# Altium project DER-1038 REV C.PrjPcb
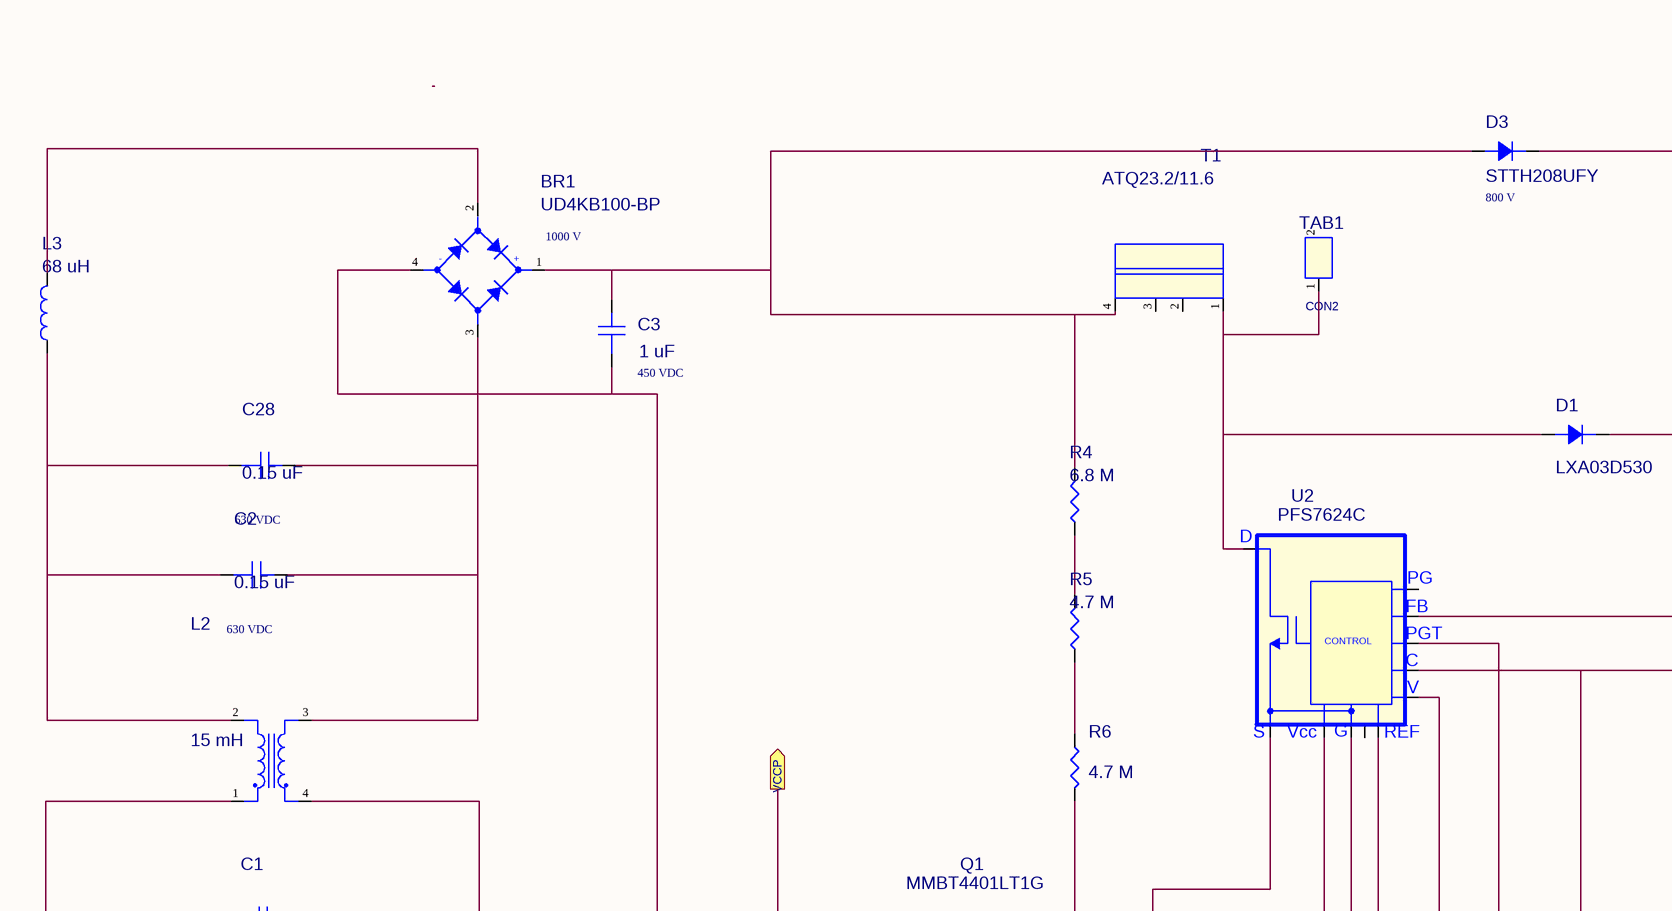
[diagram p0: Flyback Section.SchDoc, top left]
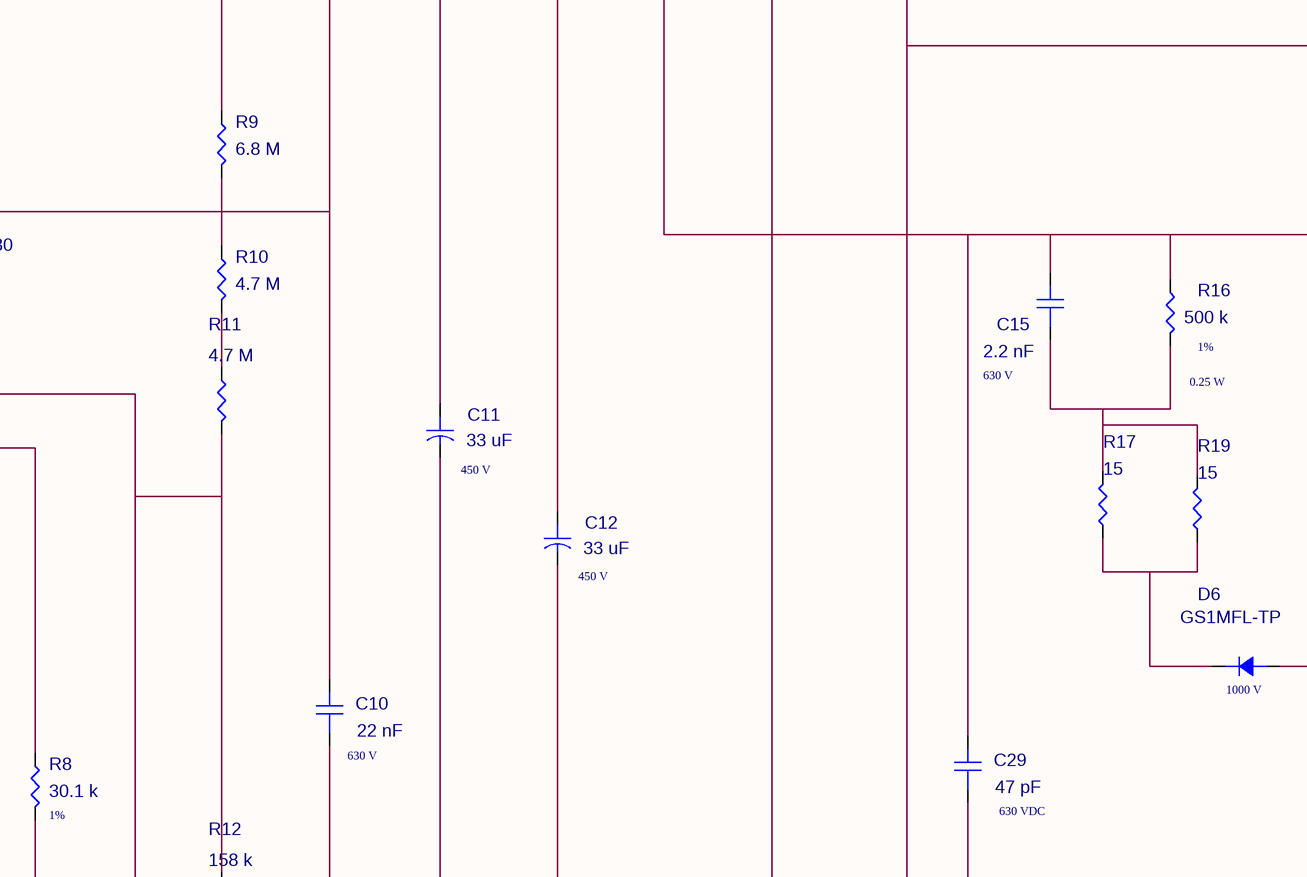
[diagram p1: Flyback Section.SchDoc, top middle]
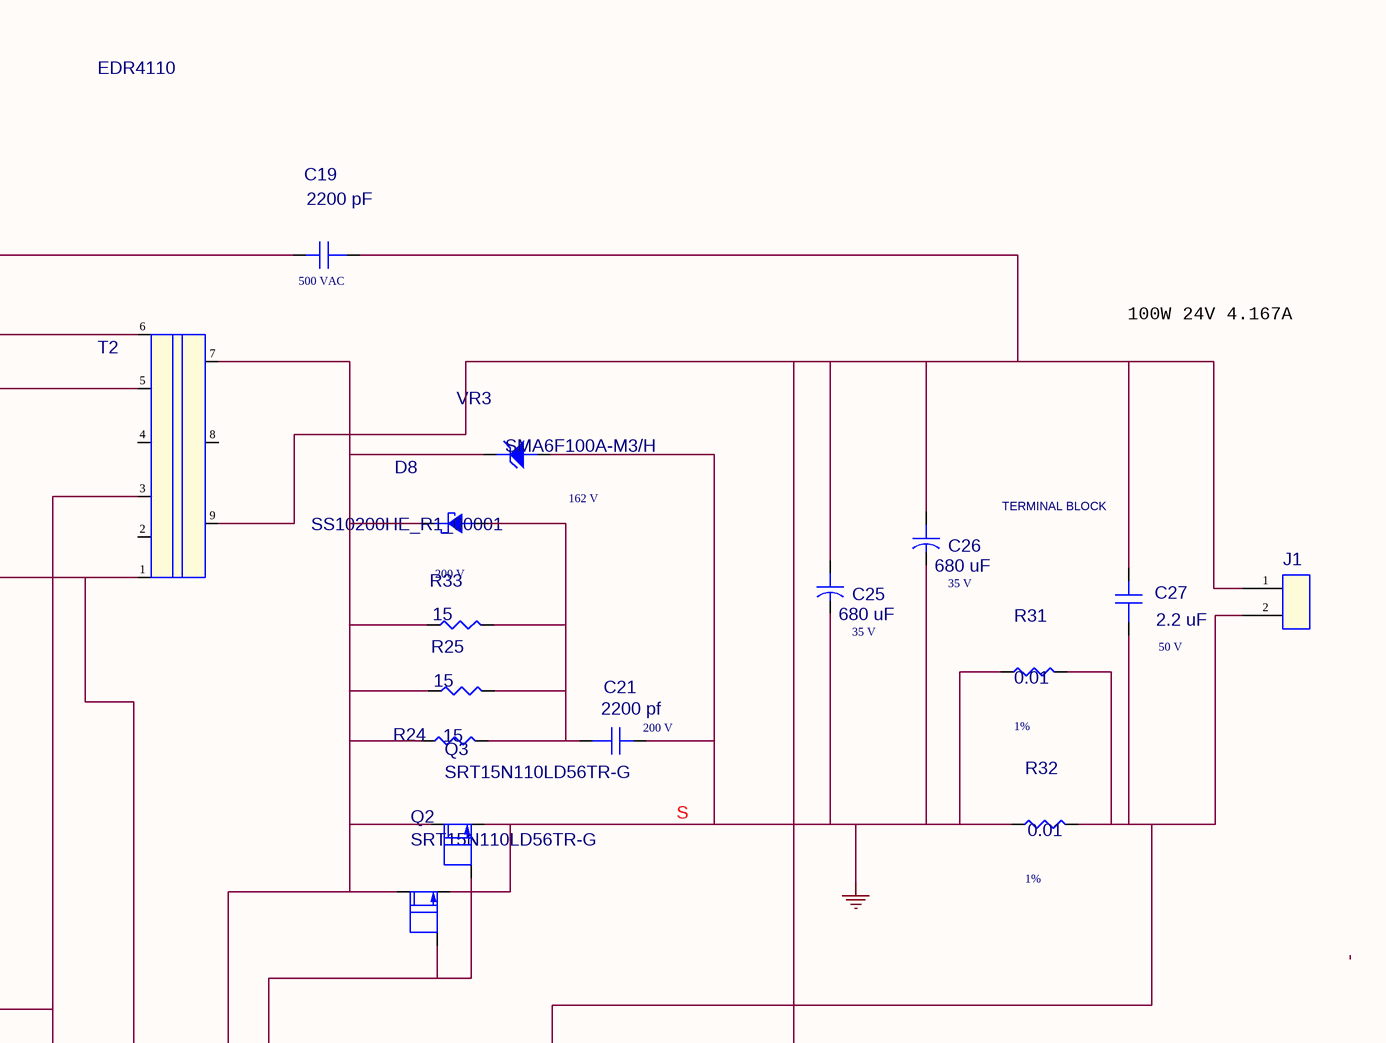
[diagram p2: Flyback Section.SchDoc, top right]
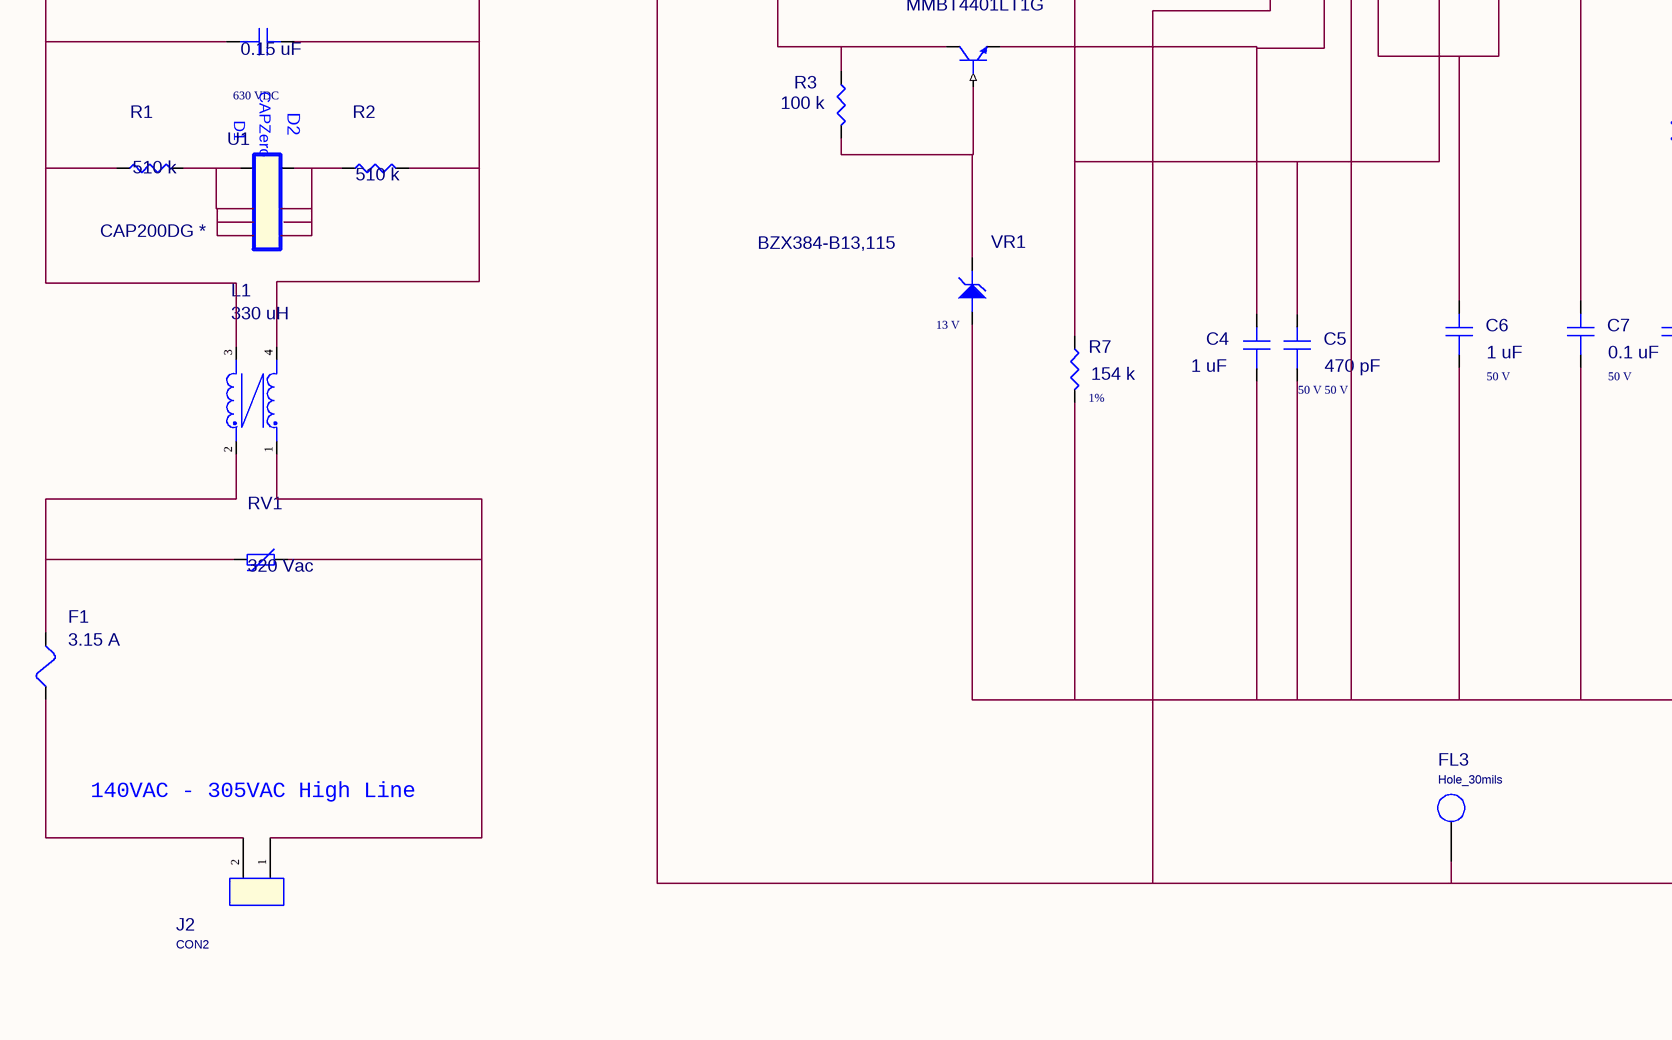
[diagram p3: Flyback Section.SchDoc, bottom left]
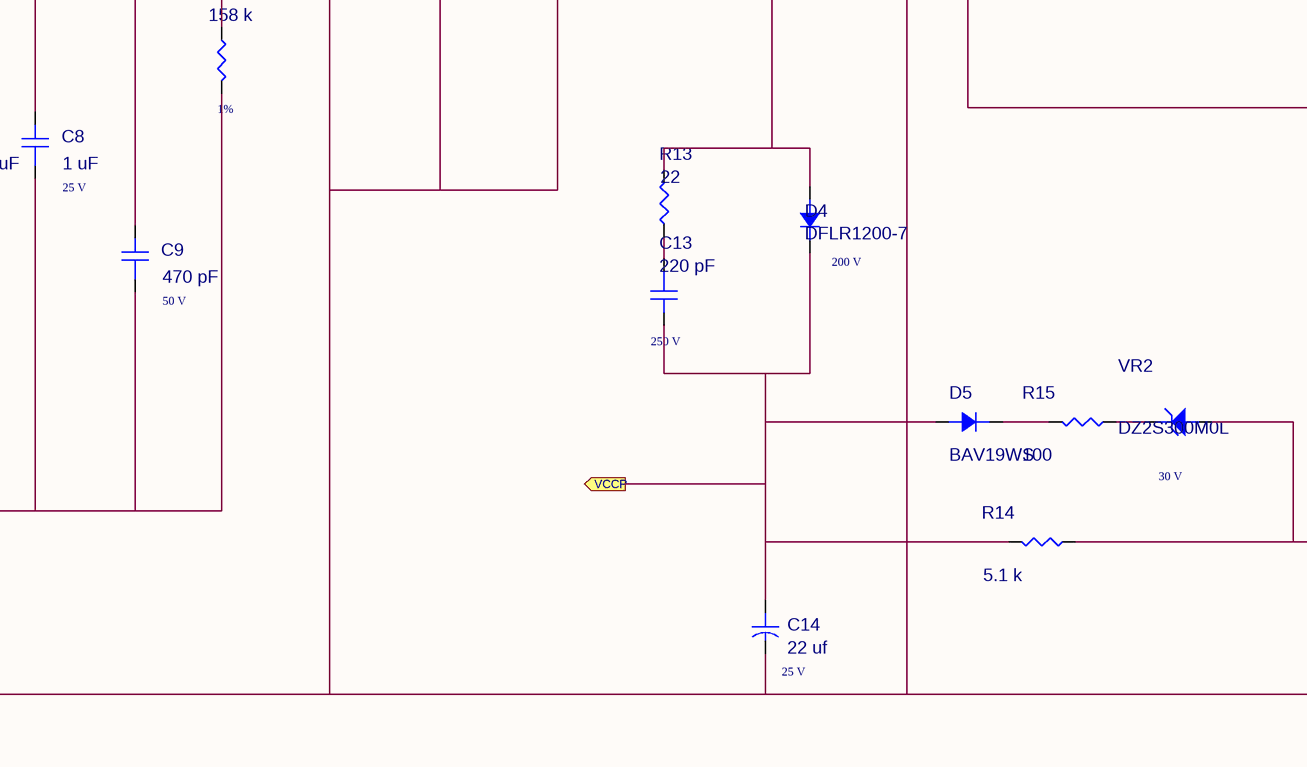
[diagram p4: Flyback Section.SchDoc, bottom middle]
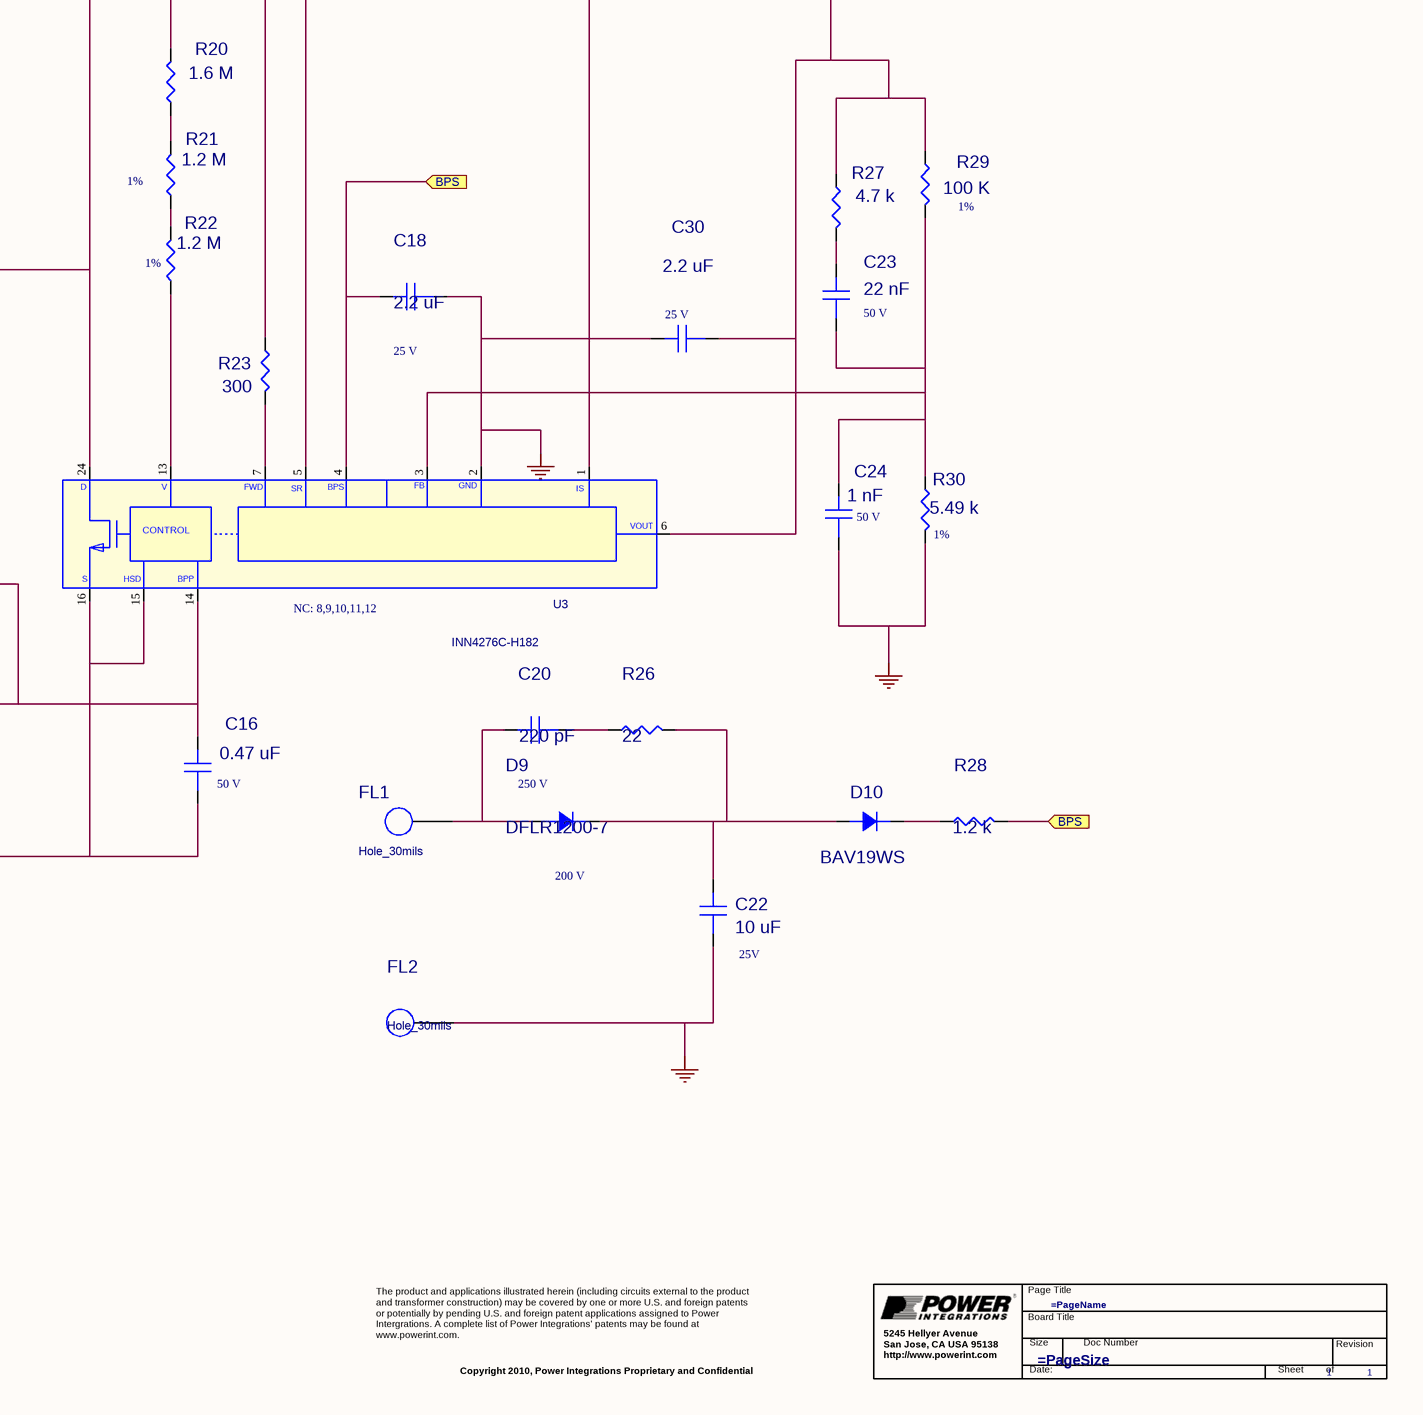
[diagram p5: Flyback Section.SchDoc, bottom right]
1 sheet, 93 parts. Net scope: flat (ports and power ports of the same name join across sheets).
Board file: DER-1038 REV C.PcbDoc

## Sheet Flyback Section.SchDoc
size 817 x 513 mm; Page Create Date: March  8, 1995; Page Number: 1; Page Size: D; Page Count: 1; Comment: TitleBlockPI_A-Sheet; Page Name: Flyback Section; DsnPath: F:\Apps_Files\Public\Design Example Reports\DER-1038 100W 24V HLO Inno4-QR\Schematic&PCB\Rev C\Altium\DER-1038 REV C.DSN; SchematicName: SCHEMATIC1; PageName: Flyback Section; PageSize: D; TopSchematic: True

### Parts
*  Page Count: 1  (hidden comment: TitleBlockPI_A-Sheet)  (graphical)
BR1  UD4KB100-BP  Disp_Voltage: 1000 V  [pidaxbridgeD3K]
C1  0.15 uF  Disp_Voltage: 630 VDC  [RAD/.250X.125/LS.200/.031]
C2  0.15 uF  Disp_Voltage: 630 VDC  [RAD/.250X.125/LS.200/.031]
C3  1 uF  Disp_Voltage: 450 VDC  [RAD/.250X.125/LS.200/.031]
C4  1 uF  Disp_Voltage: 50 V  [RAD/.250X.125/LS.200/.031]
C5  470 pF  Disp_Voltage: 50 V  [RAD/.250X.125/LS.200/.031]
C6  1 uF  Disp_Voltage: 50 V  [RAD/.250X.125/LS.200/.031]
C7  0.1 uF  Disp_Voltage: 50 V  [RAD/.250X.125/LS.200/.031]
C8  1 uF  Disp_Voltage: 25 V  [RAD/.250X.125/LS.200/.031]
C9  470 pF  Disp_Voltage: 50 V  [RAD/.250X.125/LS.200/.031]
C10  22 nF  Disp_Voltage: 630 V  [RAD/.250X.125/LS.200/.031]
C11  33 uF  Disp_Voltage: 450 V  [pipolcapd395ls200d0401705lh]
C12  33 uF  Disp_Voltage: 450 V  [pipolcapd395ls200d0401705lh]
C13  220 pF  Disp_Voltage: 250 V  [RAD/.250X.125/LS.200/.031]
C14  22 uf  Disp_Voltage: 25 V  [pi_polcap_d200_ls80_d030]
C15  2.2 nF  Disp_Voltage: 630 V  [RAD/.250X.125/LS.200/.031]
C16  0.47 uF  Disp_Voltage: 50 V  [RAD/.250X.125/LS.200/.031]
C18  2.2 uF  Disp_Voltage: 25 V  [RAD/.250X.125/LS.200/.031]
C19  2200 pF  Disp_Voltage: 500 VAC  [RAD/.250X.125/LS.200/.031]
C20  220 pF  Disp_Voltage: 250 V  [RAD/.250X.125/LS.200/.031]
C21  2200 pf  Disp_Voltage: 200 V  [RAD/.250X.125/LS.200/.031]
C22  10 uF  Disp_Voltage: 25V  [RAD/.250X.125/LS.200/.031]
C23  22 nF  Disp_Voltage: 50 V  [RAD/.250X.125/LS.200/.031]
C24  1 nF  Disp_Voltage: 50 V  [RAD/.250X.125/LS.200/.031]
C25  680 uF  Disp_Voltage: 35 V  [pipolcapclyd10mmD30]
C26  680 uF  Disp_Voltage: 35 V  [pipolcapclyd10mmD30]
C27  2.2 uF  Disp_Voltage: 50 V  [RAD/.250X.125/LS.200/.031]
C28  0.15 uF  Disp_Voltage: 630 VDC  [RAD/.250X.125/LS.200/.031]
C29  47 pF  Disp_Voltage: 630 VDC  [RAD/.250X.125/LS.200/.031]
C30  2.2 uF  Disp_Voltage: 25 V  [RAD/.250X.125/LS.200/.031]
D1  LXA03D530  [pi_sm_diode_so8c]
D3  STTH208UFY  Disp_Voltage: 800 V  [pismdo221AA]
D4  DFLR1200-7  Disp_Voltage: 200 V  [pismddflr120012]
D5  BAV19WS  [pismsod323]
D6  GS1MFL-TP  Disp_Voltage: 1000 V  [pismdo221AA]
D8  SS10200HE_R1_00001  Disp_Voltage: 200 V  [DAX1/.500X.225/.062]
D9  DFLR1200-7  Disp_Voltage: 200 V  [pismddflr120012]
D10  BAV19WS  [pismsod323]
F1  3.15 A  [pi_rst_microfuse]
FL1  Hole_30mils  [pi_hole_30mil]
FL2  Hole_30mils  [pi_hole_30mil]
FL3  Hole_30mils  [pi_hole_30mil]
J1  TERMINAL BLOCK  [pi_term_block_2pin_ls200]
J2  CON2  [CONN_1707027_PXC]
L1  330 uH  [pi_4p_ls5w4p8xd11p5mmd40]
L2  15 mH  [piind4p965x571ls736x394d040]
L3  68 uH  [pi2p14Dx6mmWd060]
Q1  MMBT4401LT1G  [pismsot23123_1]
Q2  SRT15N110LD56TR-G  [pismpqfn5x6b]
Q3  SRT15N110LD56TR-G  [pismpqfn5x6b]
R1  510 k  [pismr1206]
R2  510 k  [pismr1206]
R3  100 k  [pismr0603]
R4  6.8 M  [pismr1206]
R5  4.7 M  [pismr0805]
R6  4.7 M  [pismr0805]
R7  154 k  Disp_Tol: 1%  [pismr0603]
R8  30.1 k  Disp_Tol: 1%  [pismr0402]
R9  6.8 M  [pismr1206]
R10  4.7 M  [pismr0805]
R11  4.7 M  [pismr0805]
R12  158 k  Disp_Tol: 1%  [pismr0603]
R13  22  [pismr0603]
R14  5.1 k  [pismr0603]
R15  100  [pismr0603]
R16  500 k  Disp_Power: 0.25 W  Disp_Tol: 1%  [pismr1206]
R17  15  [pismr0805]
R19  15  [pismr0805]
R20  1.6 M  [pismr1206]
R21  1.2 M  Disp_Tol: 1%  [pismr0805]
R22  1.2 M  Disp_Tol: 1%  [pismr0805]
R23  300  [pismr0603]
R24  15  [pismr1206]
R25  15  [pismr1206]
R26  22  [pismr0603]
R27  4.7 k  [pismr0603]
R28  1.2 k  [pismr0603]
R29  100 K  Disp_Tol: 1%  [pismr0603]
R30  5.49 k  Disp_Tol: 1%  [pismr0603]
R31  0.01  Disp_Tol: 1%  [pismr1206]
R32  0.01  Disp_Tol: 1%  [pismr1206]
R33  15  [pismr1206]
RV1  320 Vac  [pidisc500x225ls335x140040]
T1  ATQ23.2/11.6  [pi_bobbin_ATQ23_V_4Pb]
T2  EDR4110  [pi_bobbin_EDR4110_9p_6x3]
TAB1  CON2  [pi_conn_qc_tab_2pin_ls200]
U1  CAP200DG *  [pi_ic_smd_so8_capzero]
U2  PFS7624C  [PI_IC_INSOP24B]
U3  INN4276C-H182  NC: 8,9,10,11,12  [pi_ic_insop_24d_IPC]
VR1  BZX384-B13,115  Disp_Voltage: 13 V  [DIO/W.80/LS.400/.030]
VR2  DZ2S300M0L  Disp_Voltage: 30 V  [DIO/W.80/LS.400/.030]
VR3  SMA6F100A-M3/H  Disp_Voltage: 162 V  [DIO/W.80/LS.400/.030]

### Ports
BPS (in), VCCP (out)

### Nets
S: C18.2 C21.1 C22.2 C24.2 C25.2 C26.2 C30.1 FL2.1 Q2.1(S) Q3.1(S) R30.2 R31.1 R32.1 U3.2 VR3.2  [also labelled GND]
NetBR1_1: BR1.1(+DC) C3.1 D3.2 R4.2 T1.4
NetBR1_2: BR1.2(AC1) L3.2
NetBR1_3: BR1.3(AC2) C2.1 C28.1 L2.3
NetBR1_4: BR1.4(-DC) C3.2 C10.2 C11.2 C12.2 C14.2 C16.2 C19.1 FL3.1 T2.5 U2.24(S) U3.15 U3.16
NetC1_1: C1.1 L1.4 L2.4 R2.2
NetC1_2: C1.2 L1.3 L2.1 R1.1
NetC2_2: C2.2 C28.2 L2.2 L3.1
NetC4_1: C4.1 Q1.2(EMITTER) U2.1(VCC)
NetC4_2: C4.2 C5.2 C6.2 C7.2 C8.2 C9.2 R7.2 R12.1 U2.2(G) VR1.2
NetC5_1: C5.1 R6.2 R7.1 U2.4(V)
NetC6_1: C6.1 U2.3(REF) U2.8(PGT)
NetC7_1: C7.1 R8.1 U2.5(C)
NetC8_1: C8.1 R8.2
NetC9_1: C9.1 R11.1 R12.2 U2.6(FB)
NetC10_1: C10.1 C11.1 C12.1 C15.1 C29.1 D1.8(K) D3.1 R9.1 R16.1 R20.1 T2.1
NetC13_1: C13.1 C14.1 D4.1 D5.2 Q1.3(COLLECTOR) R3.1 R14.1 ; port VCCP
NetC13_2: C13.2 R13.1
NetC15_2: C15.2 R16.2 R17.2 R19.2
NetC16_1: C16.1 R14.2 U3.14 VR2.2
NetC18_1: C18.1 R28.2 U3.4 ; port BPS
NetC19_2: C19.2 C25.1 C26.1 C27.1 C30.2 J1.1 R27.1 R29.1 T2.9 U3.6
NetC20_1: C20.1 D9.2 FL1.1
NetC20_2: C20.2 R26.1
NetC21_2: C21.2 D8.2 R24.1 R25.1 R33.1
NetC22_1: C22.1 D9.1 D10.2 R26.2
NetC23_1: C23.1 R27.2
NetC23_2: C23.2 C24.1 R29.2 R30.1 U3.3
NetC27_2: C27.2 J1.2 R31.2 R32.2 U3.1
NetC29_2: C29.2 D6.2 T2.3 U3.24
NetD1_1: D1.1(A) T1.1 TAB1.1 U2.16(D)
NetD4_2: D4.2 R13.2 T2.6
NetD5_1: D5.1 R15.2
NetD6_1: D6.1 R17.1 R19.1
NetD8_1: D8.1 Q2.5(D) Q3.5(D) R23.1 R24.2 R25.2 R33.2 T2.7 VR3.1
NetD10_1: D10.1 R28.1
NetF1_1: F1.1 J2.2
NetF1_2: F1.2 L1.2 RV1.2
NetJ2_1: J2.1 L1.1 RV1.1
NetQ1_1: Q1.1(BASE) R3.2 VR1.1
NetQ2_4: Q2.4(G) Q3.4(G) U3.5
NetR1_2: R1.2 U1.1(NC1) U1.2(D1) U1.3(NC2) U1.4(NC3)
NetR2_1: R2.1 U1.5(NC4) U1.7(D2) U1.8(NC8)
NetR4_1: R4.1 R5.2
NetR5_1: R5.1 R6.1
NetR9_2: R9.2 R10.1
NetR10_2: R10.2 R11.2
NetR15_1: R15.1 VR2.1
NetR20_2: R20.2 R21.1
NetR21_2: R21.2 R22.1
NetR22_2: R22.2 U3.13
NetR23_2: R23.2 U3.7

Not connected (* = marked no-connect by the designer): Q2 2(S2) 3(S3) 6(D6) 7(D7) 8(D8); Q3 2(S2) 3(S3) 6(D6) 7(D7) 8(D8); T1 2 3; T2 2 4 8; TAB1 2; U1 6(NC5); U2 7(PG) 12(G12)

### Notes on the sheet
- 100W 24V 4.167A
- 140VAC - 305VAC High Line

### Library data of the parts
BR1 = DISCRETE BRIDGE_+~~-: Part Reference: BR1; Part Number: 15-01213-00; FPLIST: pidaxbridgeD3K,pidaxbridgeD3K_horz; ALT_SYMBOLS: pidaxbridgeD3K_horz
C1 = CAP NP: Part Reference: C1; Part Number: 20-02046-00; ROOM: 1; PCB Footprint: pinpxcaprad13x6mm040; FPLIST: pinpxcaprad13x6mm040,pinpxcaprad13x6x12Hmm040; ALT_SYMBOLS: pinpxcaprad13x6x12Hmm040
C2 = CAP NP: Part Reference: C2; Part Number: 20-02046-00; ROOM: 1; PCB Footprint: pinpxcaprad13x6mm040; FPLIST: pinpxcaprad13x6mm040,pinpxcaprad13x6x12Hmm040; ALT_SYMBOLS: pinpxcaprad13x6x12Hmm040
C3 = CAP NP: Part Reference: C3; Part Number: 20-01652-00; PCB Footprint: pinpcaprad17p5x7p8x15mmLS; FPLIST: pinpcaprad17p5x7p8x15mmLS,pinpcaprad17p5x15mmLSH; ALT_SYMBOLS: pinpcaprad17p5x15mmLSH
C4 = CAP NP: Part Reference: C4; Part Number: 20-01555-00; FPLIST: pismc0603,Unisem_RMCF0603UL; ROOM: 2; ALT_SYMBOLS: Unisem_RMCF0603UL; PCB Footprint: pismc0603
C5 = CAP NP: Part Reference: C5; Part Number: 20-00510-00; PCB Footprint: pismc0603; ROOM: 2
C6 = CAP NP: Part Reference: C6; Part Number: 20-01555-00; PCB Footprint: pismc0603; ALT_SYMBOLS: Unisem_RMCF0603UL; FPLIST: pismc0603,Unisem_RMCF0603UL; ROOM: 2
C7 = CAP NP: Part Reference: C7; Part Number: 20-01434-00; PCB Footprint: pismc0603; ROOM: 2; FPLIST: pismc0603,Unisem_RMCF0603UL,cc0603; ALT_SYMBOLS: Unisem_RMCF0603UL,cc0603
C8 = CAP NP: Part Reference: C8; Part Number: 20-09151-00; PCB Footprint: pismr0402; ROOM: 2; FPLIST: pismr0402,pismr0402_1; ALT_SYMBOLS: pismr0402_1
C9 = CAP NP: Part Reference: C9; Part Number: 20-01167-00; PCB Footprint: pismc0603; ROOM: 2
C10 = CAP NP: Part Reference: C10; Part Number: 20-00732-00; PCB Footprint: pismc1210
C11 = CAP POL: Part Reference: C11; Part Number: 20-01110-00
C12 = CAP POL: Part Reference: C12; Part Number: 20-01110-00
C13 = CAP NP: Part Reference: C13; Part Number: 20-00840-00; ALT_SYMBOLS: Unisem_RMCF0603UL; FPLIST: pismc0603,Unisem_RMCF0603UL; PCB Footprint: pismc0603
C14 = CAP POL_Dup1: Part Reference: C14; Part Number: 20-08719-00
C15 = CAP NP: Part Reference: C15; Part Number: 20-08609-00; ALT_SYMBOLS: CAP_3216_TDK; FPLIST: pismc1206,CAP_3216_TDK; ROOM: 3; PCB Footprint: pismc1206
C16 = CAP NP: Part Reference: C16; Part Number: 20-09197-00; PCB Footprint: pismc0805; ALT_SYMBOLS: Unisem_RMCF0805UL; FPLIST: pismc0805,Unisem_RMCF0805UL; ROOM: 3
C18 = CAP NP: Part Reference: C18; Part Number: 20-08603-00; PCB Footprint: pismc0805; ROOM: 4
C19 = CAP NP: Part Reference: C19; Part Number: 20-01402-00; PCB Footprint: pinpcaprad11x6mmd030
C20 = CAP NP: Part Reference: C20; Part Number: 20-00840-00; FPLIST: pismc0603,Unisem_RMCF0603UL; ALT_SYMBOLS: Unisem_RMCF0603UL; PCB Footprint: pismc0603
C21 = CAP NP: Part Reference: C21; Part Number: 20-09233-00; PCB Footprint: pismc0805; ALT_SYMBOLS: Unisem_RMCF0805UL; FPLIST: pismc0805,Unisem_RMCF0805UL; ROOM: 4
C22 = CAP NP: Part Reference: C22; Part Number: 20-01673-00; Voltage: 25 V; FPLIST: pismc0805,Unisem_RMCF0805UL; ALT_SYMBOLS: Unisem_RMCF0805UL; PCB Footprint: pismc0805
C23 = CAP NP: Part Reference: C23; Part Number: 20-08927-00; ROOM: 4; FPLIST: pismc0603,Unisem_RMCF0603UL; ALT_SYMBOLS: Unisem_RMCF0603UL; PCB Footprint: pismc0603
C24 = CAP NP: Part Reference: C24; Part Number: 20-02141-00; ALT_SYMBOLS: Unisem_RMCF0603UL; FPLIST: pismc0603,Unisem_RMCF0603UL; ROOM: 4; PCB Footprint: pismc0603
C25 = CAP POL_Dup2: Part Reference: C25; Part Number: 20-01706-00; ALT_SYMBOLS: pipolcapclyd10x18mmD30H; COMPGROUP: 3; FPLIST: pipolcapclyd10mmD30,pipolcapclyd10x18mmD30H; ROOM: 4
C26 = CAP POL_Dup2: Part Reference: C26; Part Number: 20-01706-00; ROOM: 4; FPLIST: pipolcapclyd10mmD30,pipolcapclyd10x18mmD30H; COMPGROUP: 3; ALT_SYMBOLS: pipolcapclyd10x18mmD30H
C27 = CAP NP: Part Reference: C27; Part Number: 20-01545-00; PCB Footprint: pismc0805; FPLIST: pismc0805,Unisem_RMCF0805UL; ALT_SYMBOLS: Unisem_RMCF0805UL
C28 = CAP NP: Part Reference: C28; Part Number: 20-02046-00; PCB Footprint: pinpxcaprad13x6mm040; ALT_SYMBOLS: pinpxcaprad13x6x12Hmm040; FPLIST: pinpxcaprad13x6mm040,pinpxcaprad13x6x12Hmm040; ROOM: 1
C29 = CAP NP: Part Reference: C29; Part Number: 20-01456-00; PCB Footprint: pismc1206
C30 = CAP NP: Part Reference: C30; Part Number: 20-08603-00; ROOM: 4; PCB Footprint: pismc0805
D1 = DIODE_A1K8: Part Reference: D1; Part Number: 15-01126-00
D3 = DIODE: Part Reference: D3; Part Number: 15-02058-00; ROOM: 2
D4 = DIODE: Part Reference: D4; Part Number: 15-01019-00
D5 = DIODE_Dup2: Part Reference: D5; Part Number: 15-00658-00
D6 = DIODE_Dup1: Part Reference: D6; Part Number: 15-02059-00
D8 = DIODE SCHOTTKY: Part Reference: D8; Part Number: 15-01774-00; PCB Footprint: pi_sm_sod-123HE
D9 = DIODE: Part Reference: D9; Part Number: 15-01019-00
D10 = DIODE_Dup2: Part Reference: D10; Part Number: 15-00658-00
F1 = FUSE: Part Reference: F1; Part Number: 40-00071-00; ROOM: 1; FPLIST: pi_rst_microfuse,pirstmicrofusehoz; ALT_SYMBOLS: pirstmicrofusehoz
FL1 = FlyingLead: Part Reference: FL1; Part Number: 35-00284-00; ROOM: 3
FL2 = FlyingLead: Part Reference: FL2; Part Number: 35-00284-00; ROOM: 3
FL3 = FlyingLead: Part Reference: FL3; Part Number: 35-00284-00; ROOM: 3
J1 = CON2: Part Reference: J1; Part Number: 35-00277-00
J2 = CON2: Part Reference: J2; Part Number: 35-00760-00
L1 = TORRID 4P_14_23: Part Reference: L1; Part Number: 32-00466-00
L2 = INDUCTOR_4P_1-2_4-3: Part Reference: L2; Part Number: 30-00613-00
L3 = INDUCTOR: Part Reference: L3; Part Number: 32-00411-00; ROOM: 1
Q1 = NPN_BEC: Part Reference: Q1; Part Number: 55-00152-00; ROOM: 2
Q2 = FET_N_SGD_123_4_5678: Part Reference: Q2; Part Number: 50-00445-00; PACK_SHORT: (S,S2,S3)(D,D6,D7,D8)
Q3 = FET_N_SGD_123_4_5678: Part Reference: Q3; Part Number: 50-00445-00; PACK_SHORT: (S,S2,S3)(D,D6,D7,D8)
R1 = R: Part Reference: R1; Part Number: 05-01417-00
R2 = R: Part Reference: R2; Part Number: 05-01417-00
R3 = R_Dup3: Part Reference: R3; Part Number: 05-01736-00; ROOM: 2
R4 = R_Dup3: Part Reference: R4; Part Number: 05-01441-00; ROOM: 2
R5 = R_Dup3: Part Reference: R5; Part Number: 05-01606-00; ROOM: 2; FPLIST: pismr0805,Unisem_RMCF0805UL; ALT_SYMBOLS: Unisem_RMCF0805UL
R6 = R_Dup3: Part Reference: R6; Part Number: 05-01606-00; ROOM: 2; FPLIST: pismr0805,Unisem_RMCF0805UL; ALT_SYMBOLS: Unisem_RMCF0805UL
R7 = R_Dup3: Part Reference: R7; Part Number: 05-01192-00; ROOM: 2; FPLIST: pismr0603,Unisem_RMCF0603UL; ALT_SYMBOLS: Unisem_RMCF0603UL
R8 = R_Dup3: Part Reference: R8; Part Number: 05-05984-00; ROOM: 2
R9 = R_Dup3: Part Reference: R9; Part Number: 05-01441-00; ROOM: 2
R10 = R_Dup3: Part Reference: R10; Part Number: 05-01606-00; ROOM: 2; FPLIST: pismr0805,Unisem_RMCF0805UL; ALT_SYMBOLS: Unisem_RMCF0805UL
R11 = R_Dup3: Part Reference: R11; Part Number: 05-01606-00; ROOM: 2; FPLIST: pismr0805,Unisem_RMCF0805UL; ALT_SYMBOLS: Unisem_RMCF0805UL
R12 = R_Dup3: Part Reference: R12; Part Number: 05-01193-00; ROOM: 2; FPLIST: pismr0603,Unisem_RMCF0603UL; ALT_SYMBOLS: Unisem_RMCF0603UL
R13 = R_Dup3: Part Reference: R13; Part Number: 05-01648-00; ALT_SYMBOLS: Unisem_RMCF0603UL; FPLIST: pismr0603,Unisem_RMCF0603UL
R14 = R_Dup2: Part Reference: R14; Part Number: 05-01705-00; ALT_SYMBOLS: Unisem_RMCF0603UL; FPLIST: pismr0603,Unisem_RMCF0603UL; ROOM: 3
R15 = R_Dup2: Part Reference: R15; Part Number: 05-01664-00; ALT_SYMBOLS: Unisem_RMCF0603UL; FPLIST: pismr0603,Unisem_RMCF0603UL
R16 = R_Dup1: Part Reference: R16; Part Number: 05-06651-00
R17 = R_Dup1: Part Reference: R17; Part Number: 05-01475-00; ALT_SYMBOLS: Unisem_RMCF0805UL; FPLIST: pismr0805,Unisem_RMCF0805UL
R19 = R_Dup1: Part Reference: R19; Part Number: 05-01475-00; ALT_SYMBOLS: Unisem_RMCF0805UL; FPLIST: pismr0805,Unisem_RMCF0805UL
R20 = R_Dup3: Part Reference: R20; Part Number: 05-01426-00; ROOM: 3
R21 = R_Dup3: Part Reference: R21; Part Number: 05-00878-00; ROOM: 3; FPLIST: pismr0805,Unisem_RMCF0805UL; ALT_SYMBOLS: Unisem_RMCF0805UL
R22 = R_Dup3: Part Reference: R22; Part Number: 05-00878-00; ROOM: 3; FPLIST: pismr0805,Unisem_RMCF0805UL; ALT_SYMBOLS: Unisem_RMCF0805UL
R23 = R_Dup3: Part Reference: R23; Part Number: 05-01675-00; ROOM: 4; FPLIST: pismr0603,Unisem_RMCF0603UL; ALT_SYMBOLS: Unisem_RMCF0603UL
R24 = R_Dup2: Part Reference: R24; Part Number: 05-01308-00; ROOM: 4
R25 = R_Dup2: Part Reference: R25; Part Number: 05-01308-00; ROOM: 4
R26 = R_Dup3: Part Reference: R26; Part Number: 05-01648-00; FPLIST: pismr0603,Unisem_RMCF0603UL; ALT_SYMBOLS: Unisem_RMCF0603UL
R27 = R_Dup2: Part Reference: R27; Part Number: 05-01719-00; ROOM: 4; FPLIST: pismr0603,Unisem_RMCF0603UL; ALT_SYMBOLS: Unisem_RMCF0603UL
R28 = R_Dup3: Part Reference: R28; Part Number: 05-01690-00; ALT_SYMBOLS: Unisem_RMCF0603UL; FPLIST: pismr0603,Unisem_RMCF0603UL; ROOM: 4
R29 = R_Dup2: Part Reference: R29; Part Number: 05-06561-00; ROOM: 4
R30 = R_Dup3: Part Reference: R30; Part Number: 05-01149-00; ALT_SYMBOLS: Unisem_RMCF0603UL; FPLIST: pismr0603,Unisem_RMCF0603UL; ROOM: 4
R31 = R_Dup3: Part Reference: R31; Part Number: 05-06533-00
R32 = R_Dup3: Part Reference: R32; Part Number: 05-06533-00
R33 = R_Dup2: Part Reference: R33; Part Number: 05-01308-00; ROOM: 4
RV1 = VARISTOR: Part Reference: RV1; Part Number: 85-00008-00; ROOM: 1; FPLIST: pidisc500x225ls335x140040,pi_rad450x550ls300d040_h; ALT_SYMBOLS: pi_rad450x550ls300d040_h
T1 = BATQ23.2_4P/GENERIC: Part Reference: T1; Part Number: 25-01183-00
T2 = BEQ20_9P: Part Reference: T2; Part Number: 25-01139-00
TAB1 = CON1_2P_TAB: Part Reference: TAB1; Part Number: 35-00281-00; PACK_SHORT: (1,2)
U1 = CAPZero: Part Reference: U1; Part Number: 10-00958-00
U2 = HIPERPFS-4-inSOP24B: Part Reference: U2; Part Number: 10-01067-00; PACK_SHORT: (G,G12); NC: 9,10,11,13,14,15
U3 = INNO4-QR: Part Reference: U3; Part Number: 10-01500-00; FPLIST: pi_ic_insop_24d_IPC, pi_ic_insop_24d; ALT_SYMBOLS: pi_ic_insop_24d
VR1 = DIODE_ZENER_Dup1: Part Reference: VR1; Part Number: 15-00819-00; PCB Footprint: pismsod323; ROOM: 2
VR2 = DIODE_ZENER: Part Reference: VR2; Part Number: 15-00996-00; PCB Footprint: pi_sm_d_ssmini2p
VR3 = DIODE_ZENER_Dup1: Part Reference: VR3; Part Number: 15-02057-00; PCB Footprint: pismdo221AA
